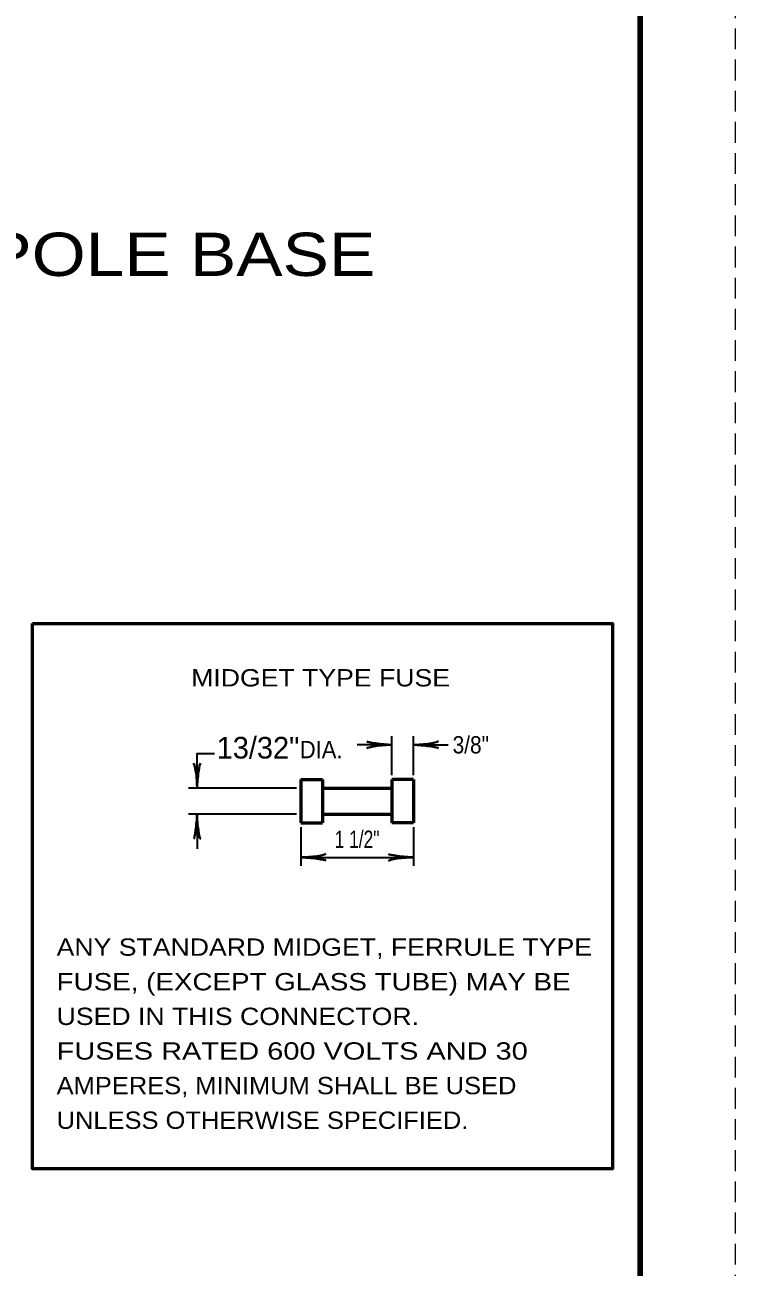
# Model space of a CAD drawing. Extents: x -1 to 679, y 0 to 440.
# Drawn here: x 596.7 to 678.7, y 152.8 to 296.3 of the extents above; entities that cross this region are included whole.
import ezdxf
from ezdxf.enums import TextEntityAlignment as Align

# ---------------------------------------------------------------- set-up
doc = ezdxf.new("R2010")
doc.units = 0
doc.header["$LTSCALE"] = 0.8
doc.linetypes.add('MEDIUM_DASHED', pattern=[4.5, 3, -1.5])
doc.layers.add('1', color=7, linetype='Continuous', lineweight=53)
doc.layers.add('61', color=7, linetype='Continuous', lineweight=35)

msp = doc.modelspace()

# ---------------------------------------------------------------- linework, layer by layer
at = {"layer": '1', "linetype": 'MEDIUM_DASHED', "lineweight": 13}
msp.add_line((678.735, 439.9088), (678.715, -0.1112), dxfattribs=at)
at = {"layer": '1', "lineweight": 35}
for p, q in [((639.0667, 209.6504), (639.0667, 214.1504)), ((641.5667, 209.6504), (641.5667, 214.1504)), ((639.0667, 213.1504), (635.0667, 213.1504)), ((641.5667, 213.1504), (645.5667, 213.1504)), ((628.0667, 208.1504), (615.5667, 208.1504)), ((628.0667, 205.1504), (615.5667, 205.1504)), ((616.5667, 205.1504), (616.5667, 201.1504)), ((628.5667, 203.6504), (628.5667, 199.1504)), ((641.5667, 203.6504), (641.5667, 199.1504)), ((628.5667, 200.1504), (641.5667, 200.1504))]:
    msp.add_line(p, q, dxfattribs=at)
at = {"layer": '1'}
for p, q in [((628.5667, 209.1504), (631.0667, 209.1504)), ((628.5667, 209.1504), (628.5667, 204.1504)), ((631.0667, 209.1504), (631.0667, 204.1504)), ((631.0667, 208.1504), (639.0667, 208.1504)), ((639.0667, 209.1504), (639.0667, 204.1504)), ((641.5667, 209.1504), (639.0667, 209.1504)), ((641.5667, 209.1504), (641.5667, 204.1504)), ((628.5667, 204.1504), (631.0667, 204.1504)), ((631.0667, 205.1504), (639.0667, 205.1504)), ((641.5667, 204.1504), (639.0667, 204.1504))]:
    msp.add_line(p, q, dxfattribs=at)
msp.add_lwpolyline([(597.5667, 227.1504), (664.5667, 227.1504), (664.5667, 164.1504), (597.5667, 164.1504)], close=True, dxfattribs=at)
at = {"layer": '1', "lineweight": 35}
msp.add_lwpolyline([(616.5667, 208.1504), (616.5667, 212.1504), (618.5667, 212.1504)], dxfattribs=at)
at = {"layer": '1', "lineweight": 40}
for centre, major_axis, ratio, start_param, end_param in [((637.9755, 212.8741), (1.7857, 0.1562), 0.122415, 0.89635335, 3.14159265), ((637.9755, 212.8741), (1.7857, 0.1562), 0.122415, 0.89635335, 3.14159265), ((637.9462, 213.362), (1.7565, -0.1757), 0.07063, 3.14071475, 5.41810995), ((637.9462, 213.362), (1.7565, -0.1757), 0.07063, 3.14071475, 5.41810995), ((642.6872, 212.9388), (-1.7565, 0.1757), 0.07063, 3.14071475, 5.41810995), ((642.6872, 212.9388), (-1.7565, 0.1757), 0.07063, 3.14071475, 5.41810995), ((642.6579, 213.4267), (-1.7857, -0.1562), 0.122415, 0.89635335, 3.14159265), ((642.6579, 213.4267), (-1.7857, -0.1562), 0.122415, 0.89635335, 3.14159265), ((616.2904, 209.2416), (0.1562, -1.7857), 0.122415, 0.89635335, 3.14159265), ((616.2904, 209.2416), (0.1562, -1.7857), 0.122415, 0.89635335, 3.14159265), ((616.7783, 209.2709), (-0.1757, -1.7565), 0.07063, 3.14071475, 5.41810995), ((616.7783, 209.2709), (-0.1757, -1.7565), 0.07063, 3.14071475, 5.41810995), ((616.3551, 204.0299), (0.1757, 1.7565), 0.07063, 3.14071475, 5.41810995), ((616.843, 204.0592), (-0.1562, 1.7857), 0.122415, 0.89635335, 3.14159265), ((629.6872, 199.9388), (-1.7565, 0.1757), 0.07063, 3.14071475, 5.41810995), ((629.6872, 199.9388), (-1.7565, 0.1757), 0.07063, 3.14071475, 5.41810995), ((629.6579, 200.4267), (-1.7857, -0.1562), 0.122415, 0.89635335, 3.14159265), ((629.6579, 200.4267), (-1.7857, -0.1562), 0.122415, 0.89635335, 3.14159265), ((640.4755, 199.8741), (1.7857, 0.1562), 0.122415, 0.89635335, 3.14159265), ((640.4462, 200.362), (1.7565, -0.1757), 0.07063, 3.14071475, 5.41810995)]:
    msp.add_ellipse(centre, major_axis=major_axis, ratio=ratio, start_param=start_param, end_param=end_param, dxfattribs=at)
at = {"layer": '61', "lineweight": 158}
msp.add_line((667.755, 429.9088), (667.775, 9.8688), dxfattribs=at)

# ---------------------------------------------------------------- texts
at = {"layer": '1', "width": 1.2}
msp.add_text('UNFUSED "Y" CONNECTOR KIT FOR POLE BASE', height=5, dxfattribs=at).set_placement((543.5786, 267.319), align=Align.CENTER)
at = {"layer": '1'}
for s, width, p in [('MIDGET TYPE FUSE', 1.15, (615.8828, 219.8937)), ('3/8"', 0.9, (646.0913, 212.1548)), ('DIA.', 0.95, (628.4304, 211.6026)), ('1 1/2"', 0.75, (632.4607, 201.2467)), ('ANY STANDARD MIDGET, FERRULE TYPE', 1.15, (600.3365, 188.7809)), ('FUSE, (EXCEPT GLASS TUBE) MAY BE', 1.2, (600.3365, 184.7809)), ('USED IN THIS CONNECTOR.', 1.15, (600.3365, 180.7809)), ('FUSES RATED 600 VOLTS AND 30', 1.25, (600.3365, 176.7809)), ('AMPERES, MINIMUM SHALL BE USED', 1.1, (600.3365, 172.7809)), ('UNLESS OTHERWISE SPECIFIED.', 1.1, (600.3365, 168.7809))]:
    msp.add_text(s, height=2, dxfattribs=dict(at, width=width)).set_placement(p)
msp.add_text('13/32"', height=2.5, dxfattribs=at).set_placement((618.83, 211.5652))

doc.saveas('drawing.dxf')
